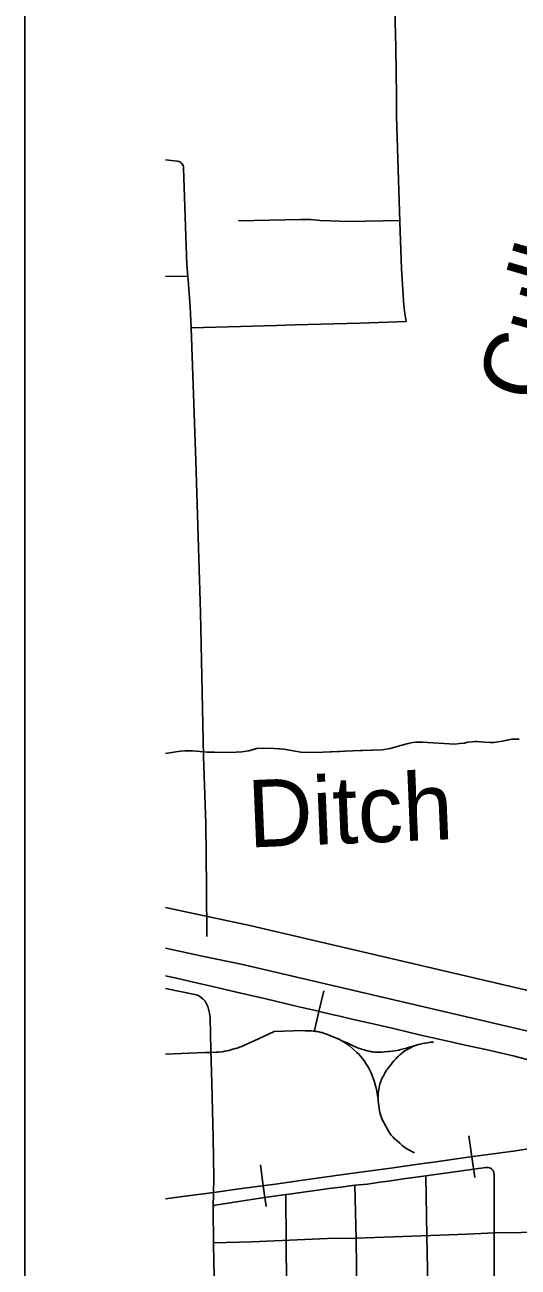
# Model space of a CAD drawing. Extents: x 309348 to 309445, y 336383 to 336484.
# Drawn here: x 309347.661 to 309348.279, y 336400.005 to 336401.564 of the extents above; entities that cross this region are included whole.
import ezdxf

# ---------------------------------------------------------------- set-up
doc = ezdxf.new("R2010")
doc.units = 0
doc.layers.add('R_Annotation', color=7, linetype='Continuous')
doc.layers.add('R_Border Notes', color=7, linetype='Continuous')

msp = doc.modelspace()

# ---------------------------------------------------------------- linework, layer by layer
at = {"layer": 'R_Annotation'}
for p, q in [((309348.0293, 336400.326), (309348.0353, 336400.3518)), ((309348.0293, 336400.326), (309348.0233, 336400.3003)), ((309348.221, 336400.1437), (309348.2173, 336400.1698)), ((309347.9595, 336400.1073), (309347.9559, 336400.1335)), ((309348.221, 336400.1437), (309348.2247, 336400.1175)), ((309347.9595, 336400.1073), (309347.963, 336400.0811))]:
    msp.add_line(p, q, dxfattribs=at)
for points in [[(309348.1308, 336401.3168), (309348.1274, 336401.4221), (309348.1268, 336401.4496), (309348.1264, 336401.4747), (309348.1256, 336401.5357), (309348.1246, 336401.5837), (309348.1224, 336401.647), (309348.1216, 336401.6707), (309348.1212, 336401.6809), (309348.1209, 336401.7001), (309348.1207, 336401.7088), (309348.1207, 336401.7088), (309348.1206, 336401.7186)], [(309347.8371, 336401.3949), (309347.8518, 336401.3932), (309347.8521, 336401.3931), (309347.8536, 336401.3927), (309347.855, 336401.3921), (309347.8563, 336401.3912), (309347.8574, 336401.3902), (309347.8584, 336401.3889), (309347.8591, 336401.3875), (309347.8595, 336401.386), (309347.8597, 336401.3844)], [(309347.8649, 336401.2486), (309347.8637, 336401.2626), (309347.8597, 336401.3844)], [(309348.1308, 336401.3185), (309348.0669, 336401.3174), (309348.0311, 336401.3187), (309348.0193, 336401.3197), (309348.0068, 336401.3198), (309347.9284, 336401.318)], [(309348.1388, 336401.1917), (309348.1372, 336401.2018), (309348.1357, 336401.2117), (309348.1328, 336401.2577), (309348.1308, 336401.3168)], [(309347.8649, 336401.2486), (309347.8371, 336401.2481)], [(309347.8692, 336401.1838), (309347.8678, 336401.2101), (309347.8653, 336401.2438), (309347.8649, 336401.2486)], [(309348.1388, 336401.1917), (309348.0811, 336401.1897), (309347.9992, 336401.1875), (309347.976, 336401.1867), (309347.931, 336401.1855), (309347.8692, 336401.1838)], [(309347.8888, 336400.4202), (309347.8882, 336400.4807), (309347.8878, 336400.5226), (309347.8876, 336400.5614), (309347.8845, 336400.6459), (309347.8809, 336400.8265), (309347.8749, 336401.0171), (309347.8692, 336401.1838)], [(309348.2805, 336400.6678), (309348.2756, 336400.6678), (309348.2712, 336400.6678), (309348.2595, 336400.6652), (309348.2486, 336400.6634), (309348.2439, 336400.6634), (309348.2369, 336400.6639), (309348.2276, 336400.6647), (309348.2213, 336400.6644), (309348.2159, 336400.6639), (309348.212, 336400.6626), (309348.2058, 336400.6621), (309348.1998, 336400.6616), (309348.172, 336400.6631), (309348.1588, 336400.6639), (309348.1505, 336400.6639), (309348.1471, 336400.6636), (309348.1412, 336400.6623), (309348.1334, 336400.66), (309348.1186, 336400.6561), (309348.109, 336400.6545), (309348.0719, 336400.6532), (309348.0246, 336400.6509), (309348.0067, 336400.6512), (309347.9852, 336400.6551), (309347.9728, 336400.6561), (309347.9593, 336400.6566), (309347.9512, 336400.6558), (309347.9414, 336400.653), (309347.9328, 336400.6517), (309347.9183, 336400.6509), (309347.8983, 336400.6512), (309347.8892, 336400.6512), (309347.876, 336400.6527), (309347.8703, 336400.6532), (309347.8617, 336400.6532), (309347.8555, 336400.6525), (309347.8371, 336400.6496)], [(309348.1595, 336400.6639), (309348.1588, 336400.6639), (309348.1505, 336400.6639), (309348.1471, 336400.6636), (309348.1412, 336400.6623), (309348.1334, 336400.66), (309348.1186, 336400.6561), (309348.109, 336400.6545), (309348.0814, 336400.6536)], [(309348.2251, 336400.6646), (309348.2213, 336400.6644), (309348.2159, 336400.6639), (309348.212, 336400.6626), (309348.2058, 336400.6621), (309348.1998, 336400.6616), (309348.1858, 336400.6623)], [(309348.2644, 336400.6663), (309348.2595, 336400.6652), (309348.2486, 336400.6634), (309348.2439, 336400.6634), (309348.2369, 336400.6639), (309348.2276, 336400.6647), (309348.2251, 336400.6646)], [(309347.845, 336400.6508), (309347.8371, 336400.6496)], [(309347.9499, 336400.6555), (309347.9414, 336400.653), (309347.9328, 336400.6517), (309347.9183, 336400.6509), (309347.8983, 336400.6512), (309347.8892, 336400.6512), (309347.876, 336400.6527), (309347.8712, 336400.6532)], [(309348.055, 336400.6524), (309348.0246, 336400.6509), (309348.0067, 336400.6512), (309347.9852, 336400.6551), (309347.9762, 336400.6558)], [(309347.9427, 336400.434), (309347.8956, 336400.4439), (309347.8371, 336400.4565)], [(309348.416, 336400.3337), (309348.3955, 336400.3336), (309348.3506, 336400.3396), (309348.3199, 336400.3458), (309347.9427, 336400.434)], [(309347.8371, 336400.4054), (309347.8852, 336400.395), (309347.9318, 336400.3852)], [(309347.9318, 336400.3852), (309348.3092, 336400.2969), (309348.3423, 336400.2902), (309348.3924, 336400.2835), (309348.4163, 336400.2837)], [(309347.8371, 336400.3708), (309347.8488, 336400.3681), (309347.8829, 336400.3603), (309347.8944, 336400.3577), (309347.9258, 336400.3504), (309347.9613, 336400.3421), (309347.9764, 336400.3385), (309348.0024, 336400.3324), (309348.0252, 336400.327), (309348.0438, 336400.3227), (309348.0556, 336400.3199), (309348.0724, 336400.3161), (309348.0898, 336400.3121), (309348.1228, 336400.3047), (309348.1572, 336400.2964), (309348.1983, 336400.2869), (309348.2127, 336400.2838), (309348.2388, 336400.2782), (309348.2744, 336400.2697), (309348.3042, 336400.2621)], [(309347.8371, 336400.3708), (309347.8488, 336400.3681), (309347.8829, 336400.3603), (309347.8944, 336400.3577), (309347.9258, 336400.3504), (309347.9613, 336400.3421), (309347.9764, 336400.3385), (309348.0024, 336400.3324), (309348.0252, 336400.327), (309348.0438, 336400.3227), (309348.0556, 336400.3199), (309348.0724, 336400.3161), (309348.0898, 336400.3121), (309348.1228, 336400.3047), (309348.1572, 336400.2964), (309348.1983, 336400.2869), (309348.2127, 336400.2838), (309348.2388, 336400.2782), (309348.2744, 336400.2697), (309348.3042, 336400.2621), (309348.335, 336400.255), (309348.3548, 336400.2503), (309348.3717, 336400.248), (309348.3828, 336400.2465)], [(309347.8905, 336400.3306), (309347.89, 336400.3324), (309347.8886, 336400.3357), (309347.8867, 336400.3387), (309347.8844, 336400.3414), (309347.8817, 336400.3437), (309347.8787, 336400.3456), (309347.8757, 336400.3469), (309347.8371, 336400.355)], [(309347.8966, 336400.0803), (309347.8974, 336400.1167), (309347.8967, 336400.1674), (309347.8949, 336400.2358), (309347.8937, 336400.2778), (309347.8928, 336400.3178), (309347.8926, 336400.3208), (309347.8922, 336400.3237), (309347.8905, 336400.3306)], [(309348.1493, 336400.2829), (309348.1431, 336400.2811), (309348.1392, 336400.28), (309348.1322, 336400.2782), (309348.1297, 336400.2776), (309348.1269, 336400.277), (309348.1239, 336400.2765), (309348.1211, 336400.2761), (309348.1177, 336400.2757), (309348.116, 336400.2756), (309348.1111, 336400.2752), (309348.1081, 336400.275), (309348.1061, 336400.275), (309348.1033, 336400.2749), (309348.1023, 336400.2749), (309348.1007, 336400.275), (309348.0991, 336400.2751), (309348.0974, 336400.2753), (309348.0952, 336400.2755), (309348.0926, 336400.276), (309348.09, 336400.2766), (309348.086, 336400.2777), (309348.0828, 336400.2787), (309348.0806, 336400.2795), (309348.0778, 336400.2805), (309348.0754, 336400.2815), (309348.0715, 336400.2833), (309348.0648, 336400.2865), (309348.0589, 336400.2889), (309348.0543, 336400.2912), (309348.0432, 336400.296), (309348.0402, 336400.2971), (309348.0376, 336400.298), (309348.0351, 336400.2988), (309348.0333, 336400.2994), (309348.0319, 336400.2997), (309348.0305, 336400.3), (309348.0291, 336400.3003), (309348.0271, 336400.3007), (309348.0252, 336400.301), (309348.0234, 336400.3011), (309348.0201, 336400.3015), (309348.018, 336400.3017), (309348.0148, 336400.3018), (309348.0119, 336400.3018), (309348.0086, 336400.3019), (309347.9733, 336400.3009)], [(309347.9733, 336400.3009), (309347.948, 336400.2892), (309347.9413, 336400.286), (309347.9359, 336400.2837), (309347.9325, 336400.2822), (309347.9308, 336400.2814), (309347.9288, 336400.2808), (309347.9269, 336400.2801), (309347.9243, 336400.2793), (309347.9202, 336400.2781), (309347.9166, 336400.2772), (309347.9144, 336400.2766), (309347.9122, 336400.2762), (309347.9108, 336400.276), (309347.908, 336400.2755), (309347.9035, 336400.275), (309347.9006, 336400.2747), (309347.8942, 336400.2744), (309347.8937, 336400.2744)], [(309348.1034, 336400.2183), (309348.1014, 336400.228), (309348.1006, 336400.2316), (309348.0996, 336400.2354), (309348.099, 336400.2375), (309348.0983, 336400.2398), (309348.0971, 336400.2433), (309348.0958, 336400.2465), (309348.0945, 336400.2498), (309348.0933, 336400.2525), (309348.0919, 336400.2549), (309348.0906, 336400.2571), (309348.0891, 336400.2594), (309348.0869, 336400.2628), (309348.0853, 336400.2652), (309348.0839, 336400.267), (309348.081, 336400.2704), (309348.0796, 336400.2718), (309348.0769, 336400.2746), (309348.0724, 336400.2787), (309348.0668, 336400.2835), (309348.0589, 336400.2889)], [(309348.1492, 336400.1484), (309348.1388, 336400.1542), (309348.1371, 336400.1554), (309348.1339, 336400.1578), (309348.1307, 336400.1607), (309348.1274, 336400.1636), (309348.1242, 336400.1663), (309348.1224, 336400.1681), (309348.1211, 336400.1693), (309348.1198, 336400.1709), (309348.1179, 336400.1736), (309348.1086, 336400.1905), (309348.1072, 336400.1941), (309348.1065, 336400.1961), (309348.1056, 336400.1993), (309348.1049, 336400.2036), (309348.104, 336400.211), (309348.1037, 336400.214), (309348.1035, 336400.2164), (309348.1034, 336400.2183), (309348.1035, 336400.2194), (309348.1036, 336400.221), (309348.1037, 336400.2232), (309348.1041, 336400.2254), (309348.1044, 336400.2279), (309348.1049, 336400.2311), (309348.1053, 336400.2328), (309348.1059, 336400.2349), (309348.1063, 336400.2363), (309348.1068, 336400.2378), (309348.1072, 336400.2393), (309348.1076, 336400.2404), (309348.1082, 336400.2418), (309348.1087, 336400.2428), (309348.1101, 336400.2454), (309348.1122, 336400.2492), (309348.1142, 336400.2523), (309348.1152, 336400.2536), (309348.1169, 336400.2559), (309348.1198, 336400.2596), (309348.1212, 336400.2614), (309348.1236, 336400.2644), (309348.1257, 336400.2666), (309348.1275, 336400.2686), (309348.129, 336400.27), (309348.1306, 336400.2716), (309348.1328, 336400.2734), (309348.1353, 336400.2753), (309348.1371, 336400.2764), (309348.1386, 336400.2775), (309348.1406, 336400.2786), (309348.144, 336400.2805), (309348.1461, 336400.2815), (309348.1493, 336400.2829), (309348.1502, 336400.2833), (309348.1516, 336400.2838), (309348.1558, 336400.2849), (309348.1596, 336400.2857), (309348.1625, 336400.2862), (309348.166, 336400.2868), (309348.1677, 336400.287), (309348.1698, 336400.2873), (309348.1711, 336400.2875), (309348.172, 336400.2875), (309348.1728, 336400.2875)], [(309347.8937, 336400.2744), (309347.8865, 336400.2744), (309347.8371, 336400.2722)], [(309347.8974, 336400.0989), (309347.9294, 336400.1032), (309347.978, 336400.1098), (309348.0119, 336400.1146), (309348.0661, 336400.1224), (309348.0911, 336400.1257), (309348.1196, 336400.1294), (309348.1567, 336400.1346), (309348.1661, 336400.136), (309348.1728, 336400.137), (309348.2163, 336400.143), (309348.2415, 336400.1466), (309348.2603, 336400.1488), (309348.2732, 336400.1505), (309348.2861, 336400.1526), (309348.3152, 336400.1564), (309348.3293, 336400.1576), (309348.3455, 336400.159), (309348.3617, 336400.16), (309348.379, 336400.1609), (309348.393, 336400.1617), (309348.4179, 336400.1623)], [(309347.8371, 336400.0908), (309347.8618, 336400.0941), (309347.8974, 336400.0989), (309347.9294, 336400.1032), (309347.978, 336400.1098), (309348.0119, 336400.1146), (309348.0661, 336400.1224), (309348.0911, 336400.1257), (309348.1196, 336400.1294), (309348.1567, 336400.1346), (309348.1661, 336400.136), (309348.1728, 336400.137), (309348.2163, 336400.143), (309348.2415, 336400.1466), (309348.2603, 336400.1488), (309348.2732, 336400.1505), (309348.2861, 336400.1526)], [(309348.2491, 336400.0465), (309348.2489, 336400.1217), (309348.2489, 336400.1219), (309348.2488, 336400.1234), (309348.2483, 336400.1248), (309348.2477, 336400.1262), (309348.2468, 336400.1274), (309348.2457, 336400.1284), (309348.2445, 336400.1293), (309348.2431, 336400.1299), (309348.2416, 336400.1302), (309348.2401, 336400.1303), (309348.2388, 336400.1302), (309348.1633, 336400.1196)], [(309348.1633, 336400.1196), (309348.1355, 336400.1158), (309348.1166, 336400.1132), (309348.1056, 336400.1116), (309348.0901, 336400.1094), (309348.0743, 336400.1078)], [(309348.1633, 336400.1196), (309348.1648, 336400.0446)], [(309348.0743, 336400.1078), (309348.057, 336400.1057), (309348.0423, 336400.104), (309347.9922, 336400.0968), (309347.988, 336400.0962)], [(309348.0743, 336400.1078), (309348.0759, 336400.0402)], [(309347.8371, 336400.0908), (309347.8618, 336400.0941), (309347.8974, 336400.0989)], [(309347.988, 336400.0962), (309347.9555, 336400.0915), (309347.8992, 336400.0827), (309347.8991, 336400.0827), (309347.899, 336400.0827), (309347.8989, 336400.0826), (309347.8988, 336400.0826), (309347.8987, 336400.0826), (309347.8986, 336400.0825), (309347.8985, 336400.0825), (309347.8984, 336400.0825), (309347.8983, 336400.0824), (309347.8982, 336400.0824), (309347.8981, 336400.0823), (309347.898, 336400.0822), (309347.8979, 336400.0822), (309347.8978, 336400.0821), (309347.8977, 336400.0821), (309347.8976, 336400.082), (309347.8975, 336400.0819), (309347.8975, 336400.0818), (309347.8974, 336400.0818), (309347.8973, 336400.0817), (309347.8972, 336400.0816), (309347.8972, 336400.0815), (309347.8971, 336400.0814), (309347.897, 336400.0813), (309347.897, 336400.0812), (309347.8969, 336400.0811), (309347.8969, 336400.081), (309347.8968, 336400.0809), (309347.8968, 336400.0808), (309347.8967, 336400.0807), (309347.8967, 336400.0806), (309347.8966, 336400.0805), (309347.8966, 336400.0804), (309347.8966, 336400.0803)], [(309347.988, 336400.0962), (309347.9881, 336400.0366)], [(309347.8966, 336400.0803), (309347.8972, 336400.0337)], [(309348.4207, 336400.0541), (309348.3691, 336400.0522), (309348.3292, 336400.0511), (309348.2835, 336400.0488), (309348.2489, 336400.048)], [(309347.8972, 336400.0358), (309347.9451, 336400.0371), (309348.0401, 336400.0409), (309348.0759, 336400.0415), (309348.1227, 336400.043), (309348.2154, 336400.0466), (309348.2489, 336400.048)], [(309347.9881, 336400.0366), (309347.9893, 336399.9315)], [(309348.0759, 336400.0402), (309348.0772, 336399.9351)], [(309348.1648, 336400.0446), (309348.1667, 336399.9388)], [(309348.2401, 336400.0456), (309348.2401, 336400.0456)], [(309348.2491, 336400.0465), (309348.2492, 336399.9422)], [(309347.8972, 336400.0337), (309347.8982, 336399.9928)]]:
    msp.add_lwpolyline(points, dxfattribs=at)
at = {"layer": 'R_Border Notes'}
msp.add_line((309347.6607, 336395.7269), (309347.6607, 336403.9877), dxfattribs=at)

# ---------------------------------------------------------------- texts
at = {"layer": 'R_Annotation'}
for s, height, rotation, p in [('Culberhouse', 0.084508, 73.8116, (309348.3078, 336401.086)), ('Ditch', 0.08451, 2.3708, (309347.9415, 336400.5316))]:
    msp.add_text(s, height=height, rotation=rotation, dxfattribs=at).set_placement(p)

doc.saveas('drawing.dxf')
